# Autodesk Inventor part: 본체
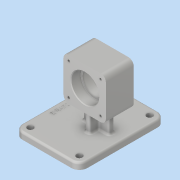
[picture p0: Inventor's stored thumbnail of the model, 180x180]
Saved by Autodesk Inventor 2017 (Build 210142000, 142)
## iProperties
Part Number: 본체
Material: 알루미늄 6061
Document SubType Name: Modeling
Designer: mrc
Density: 2.7 g/cm^3
Appearance: 알루미늄 - 평지
Mass: 683.214 g
Surface Area: 542.794 cm^2
Volume: 253.042 cm^3
Author: mrc
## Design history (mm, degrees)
sketch "스케치2"
  geometry: L1 (-32, -32)-(32, -32); L2 (32, -32)-(32, 32); L3 (32, 32)-(-32, 32); L4 (-32, 32)-(-32, -32); L5 (-32, -32)-(32, 32); L6 (32, -32)-(-32, 32); 1 further point
  constraints: 12 end point, 2 midpoint, 2 parallel, 1 horizontal, 1 perpendicular
  dimensions: "d6" = 64 distance of L3.end L2.end; "d7" = 64 distance of L2.end L1.end
extrude "돌출2" new body sketch "스케치2" distance "d8" = 42; taper "d9" = 0 deg
node "작업 평면5"
  node "작업 평면4"
sketch "스케치4"
  geometry: L1 (68, -86)-(-30, -86); L2 (-30, -86)-(-30, 44); L3 (-30, 44)-(68, 44); L4 (68, 44)-(68, -86); L5 (68, -86)-(-30, 44); L6 (-30, -86)-(68, 44); L7 (64, 0)-(0, 0) reference; L8 (0, 0)-(0, -42) reference; L9 (64, -42)-(0, -42) reference; L10 (64, 0)-(64, -42) reference; L11 (0, -42)-(64, 0); 4 further points
  constraints: 14 end point, 4 midpoint, 2 parallel, 1 horizontal, 1 horizontal alignment, 1 perpendicular
  dimensions: "d17" = 62 distance from line of L2 point (32, -21); "d18" = 130 distance of L1.end L2.end; "d19" = 98 distance of L2.end L3.end
extrude "돌출3" join sketch "스케치4" distance "d20" = 10; taper "d21" = 0 deg
sketch "스케치5"
  geometry: L1 (64, 0)-(0, 0) reference; L2 (0, 0)-(0, -42) reference; L3 (64, -42)-(0, -42) reference; L4 (64, 0)-(64, -42) reference; L5 (36, -4)-(28, -4); L6 (28, -4)-(28, -38); L7 (28, -38)-(36, -38); L8 (36, -38)-(36, -4); L9 (36, -4)-(28, -38); L10 (28, -4)-(36, -38); L11 (52, -17)-(12, -17); L12 (12, -17)-(12, -25); L13 (12, -25)-(52, -25); L14 (52, -25)-(52, -17); L15 (52, -17)-(12, -25); L16 (12, -17)-(52, -25); L17 (-30, -86)-(-30, 44) reference; L18 (-30, 44)-(68, 44) reference; 3 further points
  constraints: 24 end point, 5 midpoint, 4 parallel, 2 horizontal, 2 perpendicular
  dimensions: "d22" = 62 distance from line of point (32, -21) L17; "d23" = 65 distance from line of L18 point (32, -21); "d24" = 8 distance of L11.end L12.end; "d25" = 8 distance of L5.start L5.end; "d26" = 40 distance of L11.start L11.end; "d27" = 34 distance of L5.end L6.end
extrude "돌출4" join sketch "스케치5" stored distance "d28" = 10; taper "d29" = 0 deg
sketch "스케치6"
  geometry: C1 r 18 at (0, 0); 1 further point
  constraints: 1 centre point, 1 coincident
  dimensions: "d30" = 36 diameter of C1
extrude "돌출5" cut sketch "스케치6" stored distance "d31" = 10; taper "d32" = 0 deg
sketch "스케치7"
  geometry: C1 r 21 at (0, 0); 1 further point
  constraints: 1 centre point, 1 coincident
  dimensions: "d33" = 42 diameter of C1
extrude "돌출6" cut sketch "스케치7" distance "d34" = 15; taper "d35" = 0 deg
sketch "스케치8"
  geometry: C1 r 21 at (0, 0); 1 further point
  constraints: 1 centre point, 1 coincident
  dimensions: "d36" = 42 diameter of C1
extrude "돌출7" cut sketch "스케치8" distance "d37" = 15; taper "d38" = 0 deg
sketch "스케치9"
  geometry: C1 r 18 at (0, 0) reference; 5 further points
  constraints: 2 horizontal alignment, 2 vertical alignment
  dimensions: "d39" = 48 distance of point (24, 24) point (-24, 24); "d40" = 48 distance of point (-24, -24) point (-24, 24); "d41" = 24 horizontal distance of point (0, 0) point (-24, 24); "d42" = 24 horizontal distance of point (0, 0) point (-24, -24)
hole "구멍1" sketch "스케치9" at (-24, 24), (24, 24), (24, -24), (-24, -24) diameter "d43" = 3.242; stored, may be unused: countersink angle "d47" = 90 deg, drill point angle "d49" = 118 deg; dims "d44" = 8, "d45" = 4, "d46" = 2, "d48" = 10
node "작업 평면6"
fillet "모깎기1" dims "d51" = 12
hole "구멍2" diameter "d54" = 9; stored, may be unused: countersink angle "d58" = 90 deg, drill point angle "d60" = 118 deg; dims "d52" = 10, "d53" = 10, "d55" = 8, "d56" = 4, "d57" = 2, "d59" = 20
hole "구멍3" diameter "d63" = 9; stored, may be unused: countersink angle "d67" = 90 deg, drill point angle "d69" = 118 deg; dims "d61" = 10, "d62" = 10, "d64" = 8, "d65" = 4, "d66" = 2, "d68" = 20
hole "구멍4" diameter "d72" = 9; stored, may be unused: countersink angle "d76" = 90 deg, drill point angle "d78" = 118 deg; dims "d70" = 10, "d71" = 10, "d73" = 8, "d74" = 4, "d75" = 2, "d77" = 20
hole "구멍5" diameter "d81" = 9; stored, may be unused: countersink angle "d85" = 90 deg, drill point angle "d87" = 118 deg; dims "d79" = 10, "d80" = 10, "d82" = 8, "d83" = 4, "d84" = 2, "d86" = 20
fillet "모깎기2" dims "d88" = 3
fillet "모깎기3" dims "d89" = 8
fillet "모깎기4" dims "d90" = 3
fillet "모깎기5" dims "d91" = 3
fillet "모깎기6" dims "d92" = 3
chamfer "모따기1" distance "d93" = 1; stored, may be unused: second distance "d94" = 2, angle "d95" = 45 deg
chamfer "모따기2" distance "d96" = 1; stored, may be unused: second distance "d97" = 2, angle "d98" = 45 deg
fillet "모깎기7" dims "d99" = 0.3
sketch "스케치12"
  geometry: L1 (-18, 41)-(56, 41) reference; L2 (-27, -74)-(-27, 32) reference; L3 (56, -83)-(-18, -83) reference; L4 (65, 32)-(65, -74) reference; L5 (15, -28)-(25, -28) reference; L6 (9, -20)-(9, -22) reference; L7 (25, -14)-(15, -14) reference; L8 (25, -7)-(25, -14) reference; L9 (33, -1)-(31, -1) reference; L10 (39, -14)-(39, -7) reference; L11 (49, -14)-(39, -14) reference; L12 (55, -22)-(55, -20) reference; L13 (39, -28)-(49, -28) reference; L14 (39, -35)-(39, -28) reference; L15 (31, -41)-(33, -41) reference; L16 (25, -28)-(25, -35) reference; L17 (-30, 32)-(-30, -74) reference; L18 (56, 44)-(-18, 44) reference; C1 r 4.5 at (-18, 32) reference; C2 r 4.5 at (-18, -74) reference; C3 r 4.5 at (56, -74) reference; C4 r 4.5 at (56, 32) reference; A1 r 9 centre (56, 32) between (65, 32) and (56, 41) reference; A2 r 9 centre (-18, 32) between (-18, 41) and (-27, 32) reference; A3 r 9 centre (-18, -74) between (-27, -74) and (-18, -83) reference; A4 r 9 centre (56, -74) between (56, -83) and (65, -74) reference; A5 r 6 centre (15, -22) between (9, -22) and (15, -28) reference; A6 r 6 centre (15, -20) between (15, -14) and (9, -20) reference; A7 r 6 centre (31, -7) between (31, -1) and (25, -7) reference; A8 r 6 centre (33, -7) between (39, -7) and (33, -1) reference; A9 r 6 centre (49, -20) between (55, -20) and (49, -14) reference; A10 r 6 centre (49, -22) between (49, -28) and (55, -22) reference; A11 r 6 centre (33, -35) between (33, -41) and (39, -35) reference; A12 r 6 centre (31, -35) between (25, -35) and (31, -41) reference; 2 further points
  constraints: 1 other
  dimensions: "d100" = 10 distance from line of point (-20, -21) L17; "d101" = 65 distance from line of point (-20, -21) L18
feature "엠보싱1" sketch "스케치12" dims "d6" = 64, "d7" = 64, "d19" = 98, "d102" = 0.5, "d103" = 0
node "솔리드2"
mirror "미러1"
node "투영된 루프1"
node "투영된 루프2"
node "투영된 루프3"
other parameters: "d11" = -32, "d50" = -21
